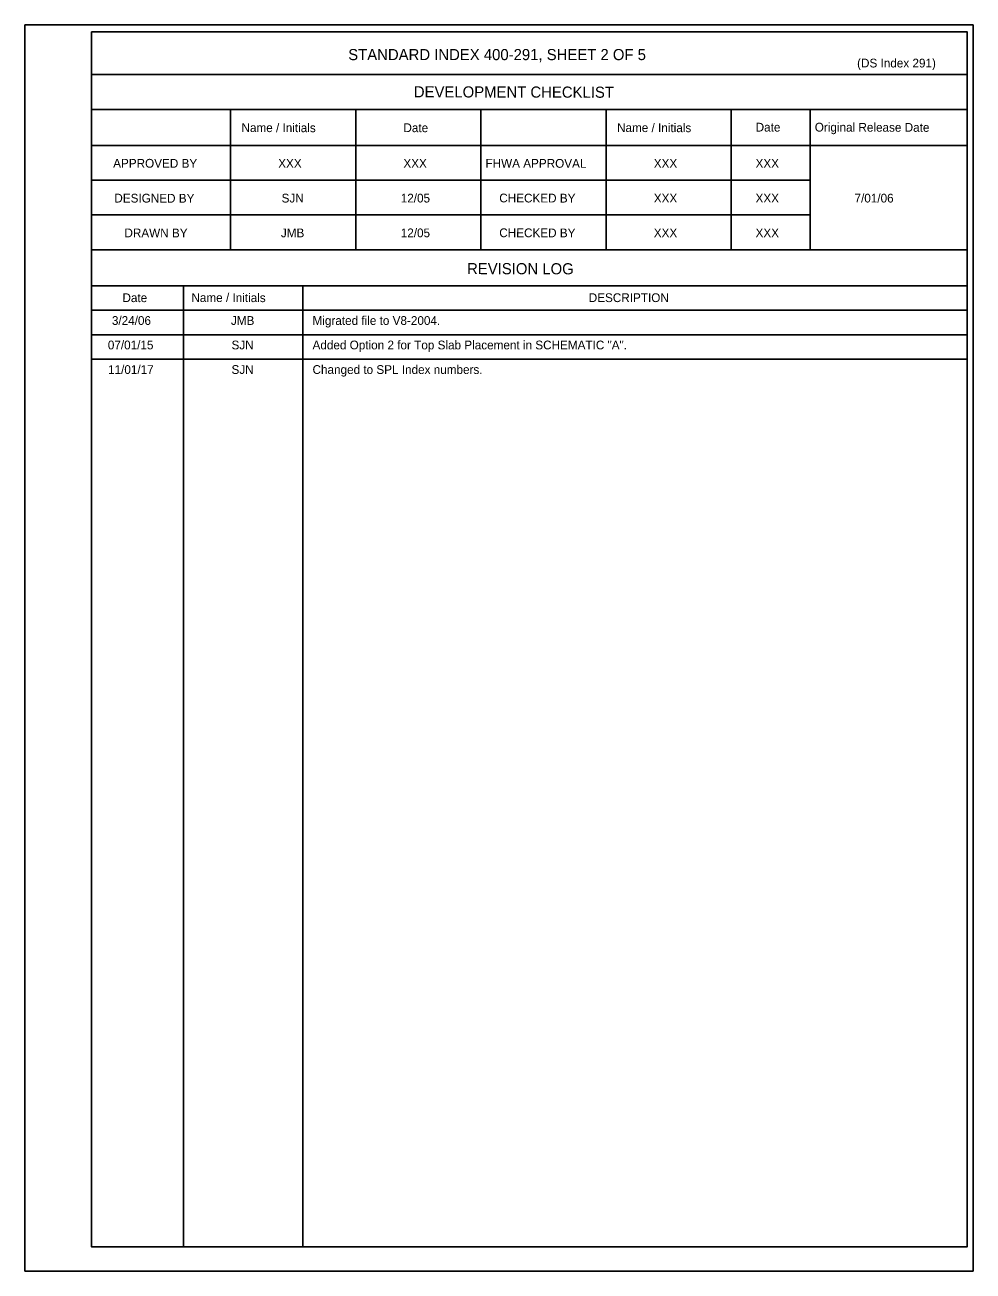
# Model space of a CAD drawing. Extents: x 10575.8 to 10606.9, y 76427.6 to 76438.8.
# Drawn here: x 10598.69 to 10606.87, y 76428.03 to 76438.78 of the extents above; entities that cross this region are included whole.
import ezdxf

# ---------------------------------------------------------------- set-up
doc = ezdxf.new("R2010")
doc.units = 0
for name, color, linetype in [('Border', 7, 'Continuous'), ('PlotBorder_dp', 7, 'Continuous'), ('SheetBorder_dp', 7, 'Continuous')]:
    doc.layers.add(name, color=color, linetype=linetype)

msp = doc.modelspace()

# ---------------------------------------------------------------- linework, layer by layer
at = {"layer": 'Border'}
for p, q in [((10606.822, 76438.349), (10599.267, 76438.349)), ((10606.822, 76438.049), (10599.267, 76438.049)), ((10600.467, 76438.049), (10600.467, 76436.839)), ((10601.547, 76438.049), (10601.547, 76436.839)), ((10602.627, 76438.049), (10602.627, 76436.839)), ((10603.707, 76438.049), (10603.707, 76436.839)), ((10604.787, 76438.049), (10604.787, 76436.839)), ((10605.467, 76438.049), (10605.467, 76436.839)), ((10606.822, 76437.739), (10599.267, 76437.739)), ((10605.467, 76437.439), (10599.267, 76437.439)), ((10605.467, 76437.139), (10599.267, 76437.139)), ((10606.822, 76436.839), (10599.267, 76436.839)), ((10606.822, 76436.528), (10599.267, 76436.528)), ((10600.062, 76436.528), (10600.062, 76428.238)), ((10601.09, 76436.528), (10601.09, 76428.238)), ((10606.822, 76436.317), (10599.267, 76436.317))]:
    msp.add_line(p, q, dxfattribs=at)
msp.add_lwpolyline([(10599.267, 76438.717), (10606.822, 76438.717), (10606.822, 76428.238), (10599.267, 76428.238)], close=True, dxfattribs=at)
at = {"layer": 'PlotBorder_dp'}
msp.add_line((10598.693, 76428.028), (10598.693, 76428.028), dxfattribs=at)
msp.add_lwpolyline([(10598.693, 76438.778), (10606.873, 76438.778), (10606.873, 76428.028), (10598.693, 76428.028)], close=True, dxfattribs=at)
at = {"layer": 'SheetBorder_dp'}
for p, q in [((10599.267, 76436.105), (10606.822, 76436.105)), ((10599.267, 76435.894), (10606.822, 76435.894))]:
    msp.add_line(p, q, dxfattribs=at)

# ---------------------------------------------------------------- texts
for s, height, p in [('STANDARD INDEX 400-291, SHEET 2 OF 5', 0.096, (10601.482, 76438.474)), ('(DS Index 291)', 0.0756, (10605.872, 76438.411)), ('XXX', 0.0756, (10600.878, 76437.546)), ('XXX', 0.0756, (10601.958, 76437.546)), ('XXX', 0.0756, (10604.118, 76437.546)), ('XXX', 0.0756, (10604.996, 76437.546)), ('SJN', 0.0756, (10600.907, 76437.246)), ('12/05', 0.0756, (10601.935, 76437.246)), ('XXX', 0.0756, (10604.118, 76437.246)), ('XXX', 0.0756, (10604.996, 76437.246)), ('7/01/06', 0.0756, (10605.85, 76437.246)), ('JMB', 0.0756, (10600.901, 76436.946)), ('12/05', 0.0756, (10601.935, 76436.946)), ('XXX', 0.0756, (10604.118, 76436.946)), ('XXX', 0.0756, (10604.996, 76436.946)), ('DESCRIPTION', 0.0756, (10603.557, 76436.387)), ('3/24/06', 0.0756, (10599.443, 76436.19)), ('JMB', 0.0756, (10600.47, 76436.19)), ('Migrated file to V8-2004.', 0.0756, (10601.174, 76436.19)), ('07/01/15', 0.0756, (10599.408, 76435.979)), ('SJN', 0.0756, (10600.475, 76435.979)), ('Added Option 2 for Top Slab Placement in SCHEMATIC "A".', 0.0756, (10601.174, 76435.979)), ('11/01/17', 0.0756, (10599.41, 76435.767)), ('SJN', 0.0756, (10600.475, 76435.767)), ('Changed to SPL Index numbers.', 0.0756, (10601.174, 76435.767))]:
    msp.add_text(s, height=height, dxfattribs=at).set_placement(p)
for s, height, p in [('DEVELOPMENT CHECKLIST', 0.096, (10602.048, 76438.153)), ('Name / Initials', 0.0756, (10600.561, 76437.854)), ('Date', 0.0756, (10601.958, 76437.853)), ('Name / Initials', 0.0756, (10603.801, 76437.854)), ('Date', 0.0756, (10604.997, 76437.858)), ('Original Release Date', 0.0756, (10605.507, 76437.858)), ('APPROVED BY', 0.0756, (10599.454, 76437.547)), ('FHWA APPROVAL', 0.0756, (10602.666, 76437.547)), ('DESIGNED BY', 0.0756, (10599.464, 76437.246)), ('CHECKED BY', 0.0756, (10602.785, 76437.247)), ('DRAWN BY', 0.0756, (10599.551, 76436.946)), ('CHECKED BY', 0.0756, (10602.785, 76436.947)), ('REVISION LOG', 0.096, (10602.507, 76436.628)), ('Date', 0.0756, (10599.534, 76436.387)), ('Name / Initials', 0.0756, (10600.129, 76436.388))]:
    msp.add_text(s, height=height, rotation=359.8756, dxfattribs=at).set_placement(p)

doc.saveas('drawing.dxf')
